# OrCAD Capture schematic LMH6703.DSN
size A
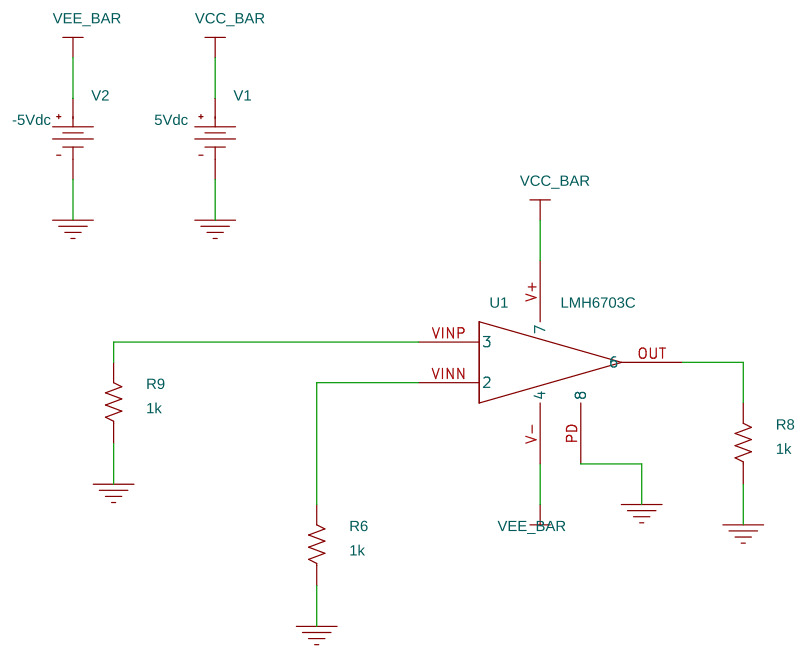
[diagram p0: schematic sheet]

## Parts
R6  1k  [AXRC05]
R8  1k  [AXRC05]
R9  1k  [AXRC05]
U1  LMH6703C
V1  VDC
V2  VDC

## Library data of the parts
R6 R8 R9 = R
U1 = LMH6703C
V1 = VDC: DC: 5Vdc
V2 = VDC: DC: -5Vdc

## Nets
VCC_BAR: U1.V+(7) V1.0(+)
VEE_BAR: U1.V-(4) V2.0(+)
0: R6.1 R8.1 R9.1 U1.PD(8) V1.1(-) V2.1(-)
N01078: R6.2 U1.VINN(2)
N01094: R8.2 U1.OUT(6)
N01272: R9.2 U1.VINP(3)
